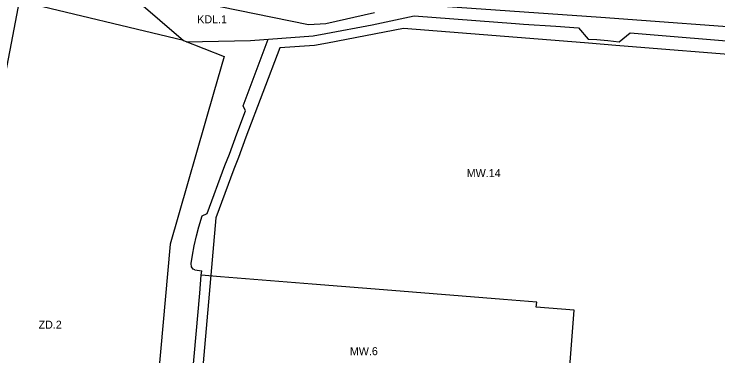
# Model space of a CAD drawing. Extents: x 7427060 to 7429122, y 5545301 to 5546237.
# Drawn here: x 7427783.1 to 7428222.9, y 5545710.8 to 5545924.5 of the extents above; entities that cross this region are included whole.
import ezdxf

# ---------------------------------------------------------------- set-up
doc = ezdxf.new("R2010")
doc.units = 0
for name, color, linetype in [('LIN_Linia Zabudowy Nieprzekraczalna', 7, 'Continuous'), ('LIN_Linie Rozgraniczajace', 7, 'Continuous'), ('TXT_Oznaczenia Przeznaczenia', 7, 'Continuous')]:
    doc.layers.add(name, color=color, linetype=linetype)

msp = doc.modelspace()

# ---------------------------------------------------------------- linework, layer by layer
at = {"layer": 'LIN_Linia Zabudowy Nieprzekraczalna'}
msp.add_lwpolyline([(7428245.15, 5545897.99), (7428161.59, 5545904.67), (7428139.66, 5545906.42), (7428026.47, 5545915.47), (7427978.93, 5545906.35), (7427970.86, 5545904.87), (7427949.14, 5545903.31), (7427927.98, 5545847.56), (7427923.31, 5545834.83), (7427920.46, 5545827.63), (7427909.28, 5545797.22), (7427905.07, 5545749.44), (7427892.52, 5545606.57)], dxfattribs=at)
at = {"layer": 'LIN_Linie Rozgraniczajace'}
for p, q in [((7427889.04, 5545907.96), (7427786.27, 5545932.57)), ((7427889.04, 5545907.96), (7427914.34, 5545897.9)), ((7427895.98, 5545764.72), (7427900.51, 5545764.03))]:
    msp.add_line(p, q, dxfattribs=at)
for points in [[(7427786.27, 5545932.57), (7427774.26, 5545870.28), (7427770.61, 5545851.37)], [(7427859.38, 5545933.64), (7427889.04, 5545907.96)], [(7428008.41, 5545925.26), (7427978.02, 5545918.41), (7427967.16, 5545917.77), (7427955.89, 5545920), (7427911.89, 5545928.89)], [(7428428.5, 5545927.32), (7428431.59, 5545913.27), (7428432.96, 5545907.07), (7428434.43, 5545900.42), (7428434.45, 5545900.33), (7428435.16, 5545897.11), (7428437.23, 5545887.71), (7428366.32, 5545901.4), (7428319.62, 5545909.88), (7428257.14, 5545914.47), (7428149.82, 5545922.39), (7428036.1, 5545930.31)], [(7427890.9, 5545907.22), (7427930.79, 5545908.01), (7427970.1, 5545910.83), (7427977.83, 5545912.25), (7428006.97, 5545917.84), (7428033.12, 5545923.39), (7428096.47, 5545918.6), (7428101.43, 5545918.25), (7428121.59, 5545916.81), (7428135.77, 5545915.81), (7428141.8, 5545908.69), (7428147.28, 5545908.54), (7428154.14, 5545907.9), (7428161.23, 5545907.2), (7428168.15, 5545912.74), (7428245.82, 5545906.26)], [(7427895.98, 5545764.72), (7427894.99, 5545765.1), (7427893.99, 5545766.59), (7427893.86, 5545768.59), (7427894.64, 5545773.82), (7427895.72, 5545779.73), (7427897.1, 5545785.89), (7427898.57, 5545791.41), (7427900.64, 5545798.35), (7427903.87, 5545799.89), (7427914.86, 5545829.77), (7427917.7, 5545836.96), (7427922.36, 5545849.66), (7427927.81, 5545864.01), (7427926.36, 5545867.17), (7427941.9, 5545908.8)], [(7427914.34, 5545897.9), (7427907.96, 5545875.71), (7427880.6, 5545780.66), (7427873.22, 5545697.05), (7427870.17, 5545678.06), (7427869.04, 5545671.02), (7427861.42, 5545623.63), (7427859.75, 5545613.18)], [(7427892.35, 5545673.17), (7427899.09, 5545749.97), (7427900.08, 5545761.2), (7427900.51, 5545764.03)], [(7428116.68, 5545657.44), (7428120.34, 5545657.9), (7428123.9, 5545659.7), (7428126.25, 5545662.7), (7428127.49, 5545666.41), (7428133.04, 5545739.52), (7428109.44, 5545741.31), (7428109.72, 5545744.4), (7428088.89, 5545746.07), (7428019.26, 5545751.65), (7427969.3, 5545755.66), (7427912.09, 5545760.24), (7427900.08, 5545761.2)]]:
    msp.add_lwpolyline(points, dxfattribs=at)

# ---------------------------------------------------------------- texts
at = {"layer": 'TXT_Oznaczenia Przeznaczenia'}
for s, p in [('KDL.1', (7427897.59, 5545918.72)), ('ZD.2', (7427798.41, 5545727.86)), ('MW.6', (7427992.97, 5545711.29))]:
    msp.add_text(s, height=5, rotation=360, dxfattribs=at).set_placement(p)
msp.add_text('MW.14', height=5, dxfattribs=at).set_placement((7428065.99, 5545822.6))

doc.saveas('drawing.dxf')
